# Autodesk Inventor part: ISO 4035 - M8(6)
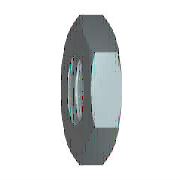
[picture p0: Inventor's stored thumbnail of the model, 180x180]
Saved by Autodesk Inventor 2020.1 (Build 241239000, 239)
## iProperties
Created: 2019-01
Part Number: ISO 4035 - M8(6)
Material: Stainless Steel, 440C
Description: Hexagon thin nuts,(chamfered)- Product grade A and B
Document SubType Name: Modeling
Standard: ISO 4035
Designer: J. Nielson
Standards Organization: BSI
Language: en-US
Size Designation: M8
Categories: <MemberInstance><Categories><Category DisplayName="Fasteners" InternalName="e4da775c-781d-43d5-af7c-5136215cf5a6" Mnemonic="FSTN"><Category DisplayName="Nuts" I
Density: 7.75 g/cm^3
Appearance: Semi-Polished
IsCustomPart: 1
Author: J. Nielson
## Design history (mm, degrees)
node "Annotations"
  node "Linear Dimension 1" dims "d0" = 11.54701 (= 1.1547 x SW), "d26" = 6, "d45" = 10 (derived)
sketch "Sketch1"
  geometry: L1 (-5.774, 0)-(-2.887, 5); L2 (-2.887, 5)-(2.887, 5); L3 (2.887, 5)-(5.774, 0); L4 (5.774, 0)-(2.887, -5); L5 (2.887, -5)-(-2.887, -5); L6 (-2.887, -5)-(-5.774, 0); 2 further points
  constraints: 12 end point, 1 coincident, 1 horizontal, 11 other
  dimensions: "d0" = 11.54701 distance of L3.end L1.start (= 1.1547 x SW)
extrude "Body" new body sketch "Sketch1" distance "d1" = 3 (= KOH); taper "d2" = 0 deg
sketch "Sketch2"
  geometry: L1 (0, 2.887)-(0, 5.774) reference; L2 (0, 5.774)-(3, 5.774) reference; L3 (3, 2.887)-(3, 5.774) reference; L4 (-0.8, 0)-(4.8, 0) reference; L5 (0.447, 5.774)-(0, 5); L6 (2.553, 5.774)-(3, 5)
  constraints: 4 end point, 4 point on line
  dimensions: "d3" = 30 deg angle of L1 L5 (= ANG1); "d4" = 30 deg angle of L3 L6 (= ANG2); "d5" = 10 diameter of L5.end L4 (= SW0); "d6" = 10 diameter of L6.end L4 (= SW01)
revolve "Chamfer1" sketch "Sketch2" stored, may be unused: angle "d7" = 90 deg
sketch "Sketch3"
  geometry: A1 r 5 centre (0, 0) between (-2.5, -4.33) and (2.5, -4.33) reference; 1 further point
  constraints: 1 coincident
hole "Thread" sketch "Sketch3" at (0, 0) diameter "d25" = 6.647; stored, may be unused: countersink angle "d29" = 82 deg, drill point angle "d31" = 118 deg; dims "d26" = 6, "d27" = 4, "d28" = 2, "d30" = 8
workaxis "Work Axis1"
workplane "Work Plane1"
body "Solid1"
chamfer "Chamfer2" distance "d8" = 0.67658 (= -0.5 x GD1 + 0.5 x NND); stored, may be unused: angle "d9" = 30 deg, second distance "d40" = 0.67658 (= -0.5 x GD1 + 0.5 x NND)
chamfer "Chamfer3" distance "d10" = 0.67658 (= -0.5 x GD1 + 0.5 x NND); stored, may be unused: angle "d11" = 30 deg, second distance "d41" = 0.67658 (= -0.5 x GD1 + 0.5 x NND)
other parameters: "ANG1" = 30 deg [user parameter; used in 1 equation term], "ANG2" = 30 deg [user parameter; used in 1 equation term], "NND" = 8 [user parameter; used in 4 equation terms], "KOH" = 3 [user parameter; used in 1 equation term], "SW0" = 10 (= SW) [user parameter; used in 1 equation term], "SW01" = 10 (= SW) [user parameter; used in 1 equation term], "GD1" = 6.64684 (computed from THREADDIA, PTC, TOA) [user parameter; used in 4 equation terms], "d13" = 0, "d14" = 0, "d39" = 0, "d42" = 0, "GUL" = 0.67658 (= 0.541266 x PTC) [user parameter], "TPU" = 8 (computed from PTC) [user parameter], "THREADDIA" = 8 [user parameter; used in 1 equation term], "TOA" = 30 deg [user parameter; used in 1 equation term], "PTC" = 1.25 [user parameter; used in 4 equation terms], "E0" = 11.55 (= 1.155 x SW) [user parameter], "GAL" = 0.67658 (= 0.541266 x PTC) [user parameter], "d43" = 7.72704 (derived), "d44" = 4.13107 (derived)
